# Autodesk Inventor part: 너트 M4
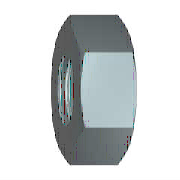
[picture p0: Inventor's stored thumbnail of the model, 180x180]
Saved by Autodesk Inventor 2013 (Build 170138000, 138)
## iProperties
Created: 2012-02
Part Number: 너트 M4
Material: 강철, 연강
Description: 6각 너트 및 6각 가는 너트 - 스타일 1
Document SubType Name: Modeling
Standard: KS B 1012
Designer: mduedu
Standards Organization: KS
Language: ko-KR
Size Designation: A M4
Categories: <MemberInstance><Categories><Category DisplayName="조임쇠" InternalName="e4da775c-781d-43d5-af7c-5136215cf5a6" Mnemonic="FSTN"><Category DisplayName="너트" InternalN
Density: 7.86 g/cm^3
Mass: 0.846697 g
Surface Area: 1.71448 cm^2
Volume: 0.107722 cm^3
IsCustomPart: 0
Author: mduedu
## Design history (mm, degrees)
sketch "스케치1"
  geometry: L1 (-4.041, 0)-(-2.021, 3.5); L2 (-2.021, 3.5)-(2.021, 3.5); L3 (2.021, 3.5)-(4.041, 0); L4 (4.041, 0)-(2.021, -3.5); L5 (2.021, -3.5)-(-2.021, -3.5); L6 (-2.021, -3.5)-(-4.041, 0); 2 further points
  constraints: 12 end point, 1 coincident, 1 horizontal, 11 other
  dimensions: "d0" = 8.0829 distance of L3.end L1.start (= 1.1547 x SW)
extrude "본체" new body sketch "스케치1" distance "d1" = 3.2 (= KOH); taper "d2" = 0 deg
sketch "스케치2"
  geometry: L1 (0, 2.021)-(0, 4.041) reference; L2 (0, 4.041)-(3.2, 4.041) reference; L3 (3.2, 2.021)-(3.2, 4.041) reference; L4 (-0.64, 0)-(3.84, 0) reference; L5 (0.313, 4.041)-(0, 3.5); L6 (2.887, 4.041)-(3.2, 3.5)
  constraints: 4 end point, 4 point on line
  dimensions: "d3" = 30 deg angle of L1 L5 (= ANG1); "d4" = 30 deg angle of L3 L6 (= ANG2); "d5" = 7 diameter of L5.end L4 (= SW0); "d6" = 7 diameter of L6.end L4 (= SW01)
revolve "모따기1" sketch "스케치2" stored, may be unused: angle "d7" = 90 deg
sketch "스케치3"
  geometry: A1 r 3.5 centre (0, 0) between (-1.75, -3.031) and (1.75, -3.031) reference; 1 further point
  constraints: 1 coincident
hole "스레드" sketch "스케치3" at (0, 0) diameter "d25" = 3.242; stored, may be unused: countersink angle "d29" = 82 deg, drill point angle "d31" = 118 deg; dims "d26" = 6, "d27" = 4, "d28" = 2, "d30" = 8
workaxis "Work Axis1"
workplane "Work Plane1"
body "Solid1"
chamfer "모따기2" distance "d8" = 0.37889 (= -0.5 x GD1 + 0.5 x NND); stored, may be unused: angle "d9" = 30 deg, second distance "d40" = 0.37889 (= -0.5 x GD1 + 0.5 x NND)
chamfer "모따기3" distance "d10" = 0.37889 (= -0.5 x GD1 + 0.5 x NND); stored, may be unused: angle "d11" = 30 deg, second distance "d41" = 0.37889 (= -0.5 x GD1 + 0.5 x NND)
other parameters: "ANG1" = 30 deg [user parameter; used in 1 equation term], "ANG2" = 30 deg [user parameter; used in 1 equation term], "NND" = 4 [user parameter; used in 4 equation terms], "KOH" = 3.2 [user parameter; used in 1 equation term], "SW" = 7 [user parameter; used in 4 equation terms], "SW0" = 7 (= SW) [user parameter; used in 1 equation term], "SW01" = 7 (= SW) [user parameter; used in 1 equation term], "GD1" = 3.24223 (computed from THREADDIA, PTC, TOA) [user parameter; used in 4 equation terms], "d13" = 0, "d14" = 0, "d39" = 0, "d42" = 0, "GUL" = 0.37889 (= 0.541266 x PTC) [user parameter], "TPU" = 14.28571 (computed from PTC) [user parameter], "THREADDIA" = 4 [user parameter; used in 1 equation term], "TOA" = 30 deg [user parameter; used in 1 equation term], "PTC" = 0.7 [user parameter; used in 4 equation terms], "E0" = 8.085 (= 1.155 x SW) [user parameter], "GAL" = 0.37889 (= 0.541266 x PTC) [user parameter]
